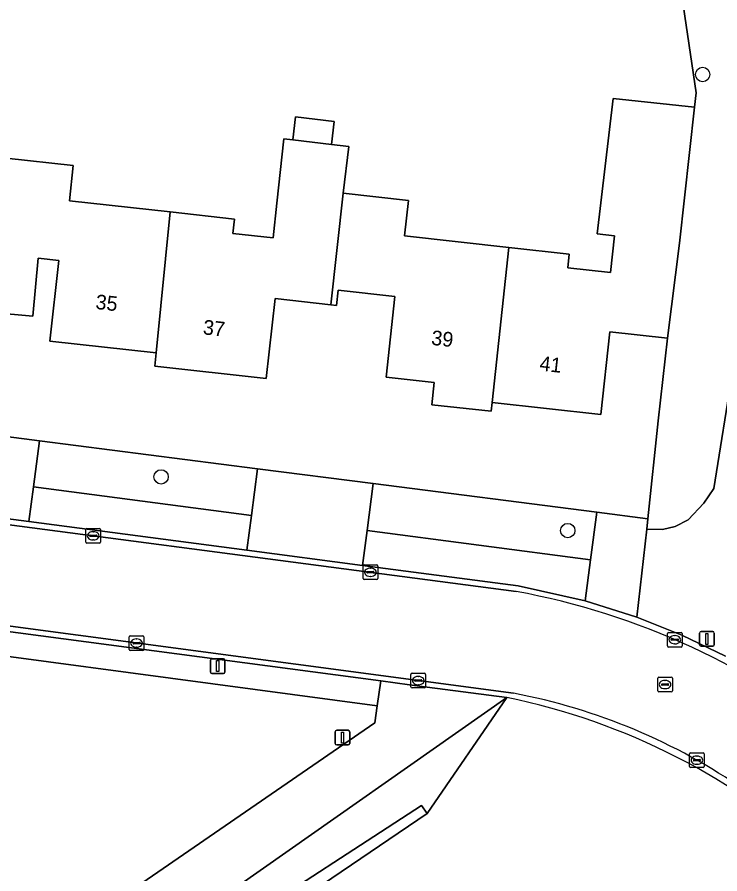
# Model space of a CAD drawing. Extents: x 162156 to 163172, y 378995 to 380779.
# Drawn here: x 162554.9 to 162602.7, y 380372 to 380430.3 of the extents above; entities that cross this region are included whole.
import ezdxf

# ---------------------------------------------------------------- set-up
doc = ezdxf.new("R2010")
doc.units = 0
for name, color, linetype in [('IMGEO_Berm_groen', 7, 'Continuous'), ('IMGEO_Boom', 7, 'Continuous'), ('IMGEO_Erf', 7, 'Continuous'), ('IMGEO_Grasland_overig', 7, 'Continuous'), ('IMGEO_Groenvoorziening', 7, 'Continuous'), ('IMGEO_Kolk', 7, 'Continuous'), ('IMGEO_Lichtmast', 7, 'Continuous'), ('IMGEO_Loofbos', 7, 'Continuous'), ('IMGEO_Naaldbos', 7, 'Continuous'), ('IMGEO_Pand', 7, 'Continuous'), ('IMGEO_Pand_nummerreeks', 7, 'Continuous'), ('IMGEO_Rijbaan_lokaal_gesloten', 7, 'Continuous'), ('IMGEO_Rioolput', 7, 'Continuous'), ('IMGEO_Voetpad_open', 7, 'Continuous'), ('IMGEO_Waterloop', 7, 'Continuous')]:
    doc.layers.add(name, color=color, linetype=linetype)

msp = doc.modelspace()

# ---------------------------------------------------------------- linework, layer by layer
at = {"layer": 'IMGEO_Berm_groen'}
for points in [[(162570.818, 380396.373), (162555.975, 380398.316), (162555.664, 380395.948), (162570.507, 380393.999)], [(162593.931, 380393.347), (162578.701, 380395.341), (162578.389, 380392.965), (162589.003, 380391.571), (162593.564, 380390.548)]]:
    msp.add_lwpolyline(points, close=True, dxfattribs=at)
at = {"layer": 'IMGEO_Boom'}
for centre in [(162601.57, 380426.397), (162564.669, 380398.997), (162592.38, 380395.341)]:
    msp.add_circle(centre, 0.489, dxfattribs=at)
at = {"layer": 'IMGEO_Erf'}
for points in [[(162554.109, 380420.701), (162558.682, 380420.192), (162558.416, 380417.799), (162565.287, 380417.035), (162569.664, 380416.548), (162569.556, 380415.575), (162572.306, 380415.269), (162572.559, 380417.632), (162573.028, 380422.024), (162573.635, 380421.951), (162573.822, 380423.507), (162576.464, 380423.19), (162576.277, 380421.634), (162577.451, 380421.493), (162577.069, 380418.312), (162581.524, 380417.816), (162581.256, 380415.406), (162588.352, 380414.617), (162592.475, 380414.158), (162592.372, 380413.232), (162595.29, 380412.908), (162595.568, 380415.405), (162594.377, 380415.538), (162595.473, 380424.77), (162601.019, 380424.181), (162601.125, 380425.141), (162599.269, 380437.761)], [(162548.501, 380402.47), (162556.387, 380401.459), (162571.235, 380399.555), (162579.121, 380398.544), (162594.356, 380396.59), (162597.84, 380396.144), (162598.548, 380402.803), (162599.176, 380408.437), (162595.256, 380408.873), (162594.629, 380403.239), (162587.218, 380404.064), (162587.153, 380403.462), (162583.112, 380403.911), (162583.281, 380405.431), (162579.994, 380405.797), (162580.602, 380411.271), (162576.742, 380411.701), (162576.628, 380410.676), (162576.226, 380410.721), (162572.44, 380411.142), (162571.834, 380405.691), (162564.238, 380406.536), (162564.328, 380407.439), (162557.097, 380408.244), (162557.707, 380413.723), (162556.282, 380413.881), (162555.936, 380409.935), (162553.143, 380410.179)]]:
    msp.add_lwpolyline(points, dxfattribs=at)
at = {"layer": 'IMGEO_Grasland_overig'}
for points in [[(162570.818, 380396.373), (162571.235, 380399.555), (162556.387, 380401.459), (162555.975, 380398.316)], [(162593.931, 380393.347), (162594.356, 380396.59), (162579.121, 380398.544), (162578.701, 380395.341)]]:
    msp.add_lwpolyline(points, close=True, dxfattribs=at)
at = {"layer": 'IMGEO_Groenvoorziening'}
for points in [[(162603.149, 380451.149), (162602.316, 380456.226), (162596.531, 380456.495), (162597.555, 380449.385), (162598.114, 380445.6), (162598.662, 380441.849), (162598.937, 380439.632), (162598.286, 380437.854), (162599.269, 380437.761), (162601.125, 380425.141), (162601.019, 380424.181), (162599.997, 380414.912), (162599.176, 380408.437), (162598.548, 380402.803), (162597.84, 380396.144), (162597.76, 380395.446), (162598.834, 380395.404), (162599.697, 380395.608), (162600.573, 380396.065), (162601.653, 380397.207), (162602.326, 380398.21), (162603.622, 380406.286)], [(162603.622, 380406.286), (162602.326, 380398.21), (162601.653, 380397.207), (162600.573, 380396.065), (162599.697, 380395.608), (162598.834, 380395.404), (162597.76, 380395.446), (162597.075, 380389.437), (162600.149, 380388.214), (162603.133, 380386.785)]]:
    msp.add_lwpolyline(points, dxfattribs=at)
msp.add_lwpolyline([(162515.462, 380331.725), (162532.467, 380343.441), (162569.479, 380368.209), (162582.423, 380376.619), (162582.8, 380376.077), (162588.216, 380383.966), (162569.893, 380371.126), (162550.741, 380358.23), (162527.032, 380341.73), (162514.906, 380333.495)], close=True, dxfattribs=at)
at = {"layer": 'IMGEO_Kolk'}
for p, q in [((162559.616, 380395.484), (162560.468, 380395.484)), ((162559.541, 380394.558), (162559.541, 380395.41)), ((162559.8, 380394.978), (162559.8, 380394.99)), ((162560.238, 380394.941), (162559.84, 380394.941)), ((162559.843, 380395.027), (162560.241, 380395.027)), ((162560.029, 380395.264), (162560.054, 380395.264)), ((162560.284, 380394.99), (162560.284, 380394.978)), ((162560.542, 380395.41), (162560.542, 380394.558)), ((162560.468, 380394.484), (162559.616, 380394.484)), ((162560.052, 380394.704), (162560.027, 380394.704)), ((162578.428, 380392.074), (162578.428, 380392.926)), ((162578.503, 380393), (162579.355, 380393)), ((162578.73, 380392.543), (162579.128, 380392.543)), ((162578.916, 380392.78), (162578.941, 380392.78)), ((162579.429, 380392.926), (162579.429, 380392.074)), ((162579.355, 380392), (162578.503, 380392)), ((162578.687, 380392.494), (162578.687, 380392.506)), ((162579.125, 380392.457), (162578.727, 380392.457)), ((162578.939, 380392.22), (162578.914, 380392.22)), ((162579.171, 380392.506), (162579.171, 380392.494)), ((162562.492, 380387.252), (162562.492, 380388.104)), ((162562.567, 380388.178), (162563.419, 380388.178)), ((162562.98, 380387.958), (162563.005, 380387.958)), ((162563.493, 380388.104), (162563.493, 380387.252)), ((162599.174, 380387.483), (162599.174, 380388.335)), ((162599.249, 380388.409), (162600.101, 380388.409)), ((162599.433, 380387.903), (162599.433, 380387.915)), ((162599.871, 380387.866), (162599.473, 380387.866)), ((162599.476, 380387.952), (162599.874, 380387.952)), ((162599.662, 380388.189), (162599.687, 380388.189)), ((162599.917, 380387.915), (162599.917, 380387.903)), ((162600.175, 380388.335), (162600.175, 380387.483)), ((162562.751, 380387.672), (162562.751, 380387.684)), ((162563.189, 380387.635), (162562.791, 380387.635)), ((162562.794, 380387.721), (162563.192, 380387.721)), ((162563.003, 380387.398), (162562.978, 380387.398)), ((162563.235, 380387.684), (162563.235, 380387.672)), ((162600.101, 380387.409), (162599.249, 380387.409)), ((162599.685, 380387.629), (162599.66, 380387.629)), ((162563.419, 380387.178), (162562.567, 380387.178)), ((162581.69, 380384.697), (162581.69, 380385.549)), ((162581.765, 380385.623), (162582.617, 380385.623)), ((162582.691, 380385.549), (162582.691, 380384.697)), ((162581.949, 380385.117), (162581.949, 380385.129)), ((162582.387, 380385.08), (162581.989, 380385.08)), ((162581.992, 380385.166), (162582.39, 380385.166)), ((162582.178, 380385.403), (162582.203, 380385.403)), ((162582.433, 380385.129), (162582.433, 380385.117)), ((162582.617, 380384.623), (162581.765, 380384.623)), ((162582.201, 380384.843), (162582.176, 380384.843)), ((162600.677, 380379.276), (162600.677, 380380.128)), ((162600.752, 380380.202), (162601.604, 380380.202)), ((162600.936, 380379.696), (162600.936, 380379.708)), ((162600.979, 380379.745), (162601.377, 380379.745)), ((162601.165, 380379.982), (162601.19, 380379.982)), ((162601.42, 380379.708), (162601.42, 380379.696)), ((162601.678, 380380.128), (162601.678, 380379.276)), ((162601.604, 380379.202), (162600.752, 380379.202)), ((162601.374, 380379.659), (162600.976, 380379.659)), ((162601.188, 380379.422), (162601.163, 380379.422))]:
    msp.add_line(p, q, dxfattribs=at)
for points in [[(162559.616, 380395.484), (162560.468, 380395.484)], [(162559.541, 380394.558), (162559.541, 380395.41)], [(162560.542, 380395.41), (162560.542, 380394.558)], [(162560.468, 380394.484), (162559.616, 380394.484)], [(162578.428, 380392.074), (162578.428, 380392.926)], [(162578.503, 380393), (162579.355, 380393)], [(162579.429, 380392.926), (162579.429, 380392.074)], [(162579.355, 380392), (162578.503, 380392)], [(162562.492, 380387.252), (162562.492, 380388.104)], [(162562.567, 380388.178), (162563.419, 380388.178)], [(162563.493, 380388.104), (162563.493, 380387.252)], [(162599.174, 380387.483), (162599.174, 380388.335)], [(162599.249, 380388.409), (162600.101, 380388.409)], [(162600.175, 380388.335), (162600.175, 380387.483)], [(162600.101, 380387.409), (162599.249, 380387.409)], [(162563.419, 380387.178), (162562.567, 380387.178)], [(162581.69, 380384.697), (162581.69, 380385.549)], [(162581.765, 380385.623), (162582.617, 380385.623)], [(162582.691, 380385.549), (162582.691, 380384.697)], [(162582.617, 380384.623), (162581.765, 380384.623)], [(162600.677, 380379.276), (162600.677, 380380.128)], [(162600.752, 380380.202), (162601.604, 380380.202)], [(162601.678, 380380.128), (162601.678, 380379.276)], [(162601.604, 380379.202), (162600.752, 380379.202)]]:
    msp.add_lwpolyline(points, dxfattribs=at)
for centre, radius, start, end in [((162559.618, 380395.408), 0.0765, 91.55205, 178.44795), ((162559.618, 380395.408), 0.0765, 91.55205, 178.44795), ((162560.466, 380395.408), 0.0765, 1.55205, 88.44795), ((162560.466, 380395.408), 0.0765, 1.55205, 88.44795), ((162559.84, 380394.987), 0.0403, 85.87752, 175.75265), ((162559.837, 380394.977), 0.0366, 178.93798, 274.71019), ((162560.241, 380394.984), 0.043, 264.86636, 352.45326), ((162560.245, 380394.989), 0.0386, 1.73085, 96.63898), ((162559.618, 380394.56), 0.0765, 181.55205, 268.44795), ((162559.618, 380394.56), 0.0765, 181.55205, 268.44795), ((162560.466, 380394.56), 0.0765, 271.55205, 358.44795), ((162560.466, 380394.56), 0.0765, 271.55205, 358.44795), ((162578.505, 380392.924), 0.0765, 91.55205, 178.44795), ((162578.505, 380392.924), 0.0765, 91.55205, 178.44795), ((162578.727, 380392.503), 0.0403, 85.87752, 175.75265), ((162579.132, 380392.505), 0.0386, 1.73085, 96.63898), ((162579.353, 380392.924), 0.0765, 1.55205, 88.44795), ((162579.353, 380392.924), 0.0765, 1.55205, 88.44795), ((162578.505, 380392.076), 0.0765, 181.55205, 268.44795), ((162578.505, 380392.076), 0.0765, 181.55205, 268.44795), ((162578.724, 380392.493), 0.0366, 178.93798, 274.71019), ((162579.128, 380392.5), 0.043, 264.86636, 352.45326), ((162579.353, 380392.076), 0.0765, 271.55205, 358.44795), ((162579.353, 380392.076), 0.0765, 271.55205, 358.44795), ((162562.569, 380388.102), 0.0765, 91.55205, 178.44795), ((162562.569, 380388.102), 0.0765, 91.55205, 178.44795), ((162563.417, 380388.102), 0.0765, 1.55205, 88.44795), ((162563.417, 380388.102), 0.0765, 1.55205, 88.44795), ((162599.251, 380388.333), 0.0765, 91.55205, 178.44795), ((162599.251, 380388.333), 0.0765, 91.55205, 178.44795), ((162599.473, 380387.912), 0.0403, 85.87752, 175.75265), ((162599.47, 380387.902), 0.0366, 178.93798, 274.71019), ((162599.874, 380387.909), 0.043, 264.86636, 352.45326), ((162599.878, 380387.914), 0.0386, 1.73085, 96.63898), ((162600.099, 380388.333), 0.0765, 1.55205, 88.44795), ((162600.099, 380388.333), 0.0765, 1.55205, 88.44795), ((162562.791, 380387.681), 0.0403, 85.87752, 175.75265), ((162562.788, 380387.671), 0.0366, 178.93798, 274.71019), ((162563.192, 380387.678), 0.043, 264.86636, 352.45326), ((162563.196, 380387.683), 0.0386, 1.73085, 96.63898), ((162599.251, 380387.485), 0.0765, 181.55205, 268.44795), ((162599.251, 380387.485), 0.0765, 181.55205, 268.44795), ((162600.099, 380387.485), 0.0765, 271.55205, 358.44795), ((162600.099, 380387.485), 0.0765, 271.55205, 358.44795), ((162562.569, 380387.254), 0.0765, 181.55205, 268.44795), ((162562.569, 380387.254), 0.0765, 181.55205, 268.44795), ((162563.417, 380387.254), 0.0765, 271.55205, 358.44795), ((162563.417, 380387.254), 0.0765, 271.55205, 358.44795), ((162581.767, 380385.547), 0.0765, 91.55205, 178.44795), ((162581.767, 380385.547), 0.0765, 91.55205, 178.44795), ((162582.615, 380385.547), 0.0765, 1.55205, 88.44795), ((162582.615, 380385.547), 0.0765, 1.55205, 88.44795), ((162581.989, 380385.126), 0.0403, 85.87752, 175.75265), ((162581.986, 380385.116), 0.0366, 178.93798, 274.71019), ((162582.39, 380385.123), 0.043, 264.86636, 352.45326), ((162582.394, 380385.128), 0.0386, 1.73085, 96.63898), ((162581.767, 380384.699), 0.0765, 181.55205, 268.44795), ((162581.767, 380384.699), 0.0765, 181.55205, 268.44795), ((162582.615, 380384.699), 0.0765, 271.55205, 358.44795), ((162582.615, 380384.699), 0.0765, 271.55205, 358.44795), ((162600.754, 380380.126), 0.0765, 91.55205, 178.44795), ((162600.754, 380380.126), 0.0765, 91.55205, 178.44795), ((162600.976, 380379.705), 0.0403, 85.87752, 175.75265), ((162600.973, 380379.695), 0.0366, 178.93798, 274.71019), ((162601.377, 380379.702), 0.043, 264.86636, 352.45326), ((162601.381, 380379.707), 0.0386, 1.73085, 96.63898), ((162601.602, 380380.126), 0.0765, 1.55205, 88.44795), ((162601.602, 380380.126), 0.0765, 1.55205, 88.44795), ((162600.754, 380379.278), 0.0765, 181.55205, 268.44795), ((162600.754, 380379.278), 0.0765, 181.55205, 268.44795), ((162601.602, 380379.278), 0.0765, 271.55205, 358.44795), ((162601.602, 380379.278), 0.0765, 271.55205, 358.44795)]:
    msp.add_arc(centre, radius, start, end, dxfattribs=at)
for centre, major_axis, ratio, start_param, end_param in [((162560.028, 380394.984), (-0.387, 0.002), 0.722429, 4.712389, 7.853982), ((162560.053, 380394.984), (-0.39, 0.002), 0.717154, 1.570796, 4.712389), ((162578.915, 380392.5), (-0.387, 0.002), 0.722429, 4.712389, 7.853982), ((162578.94, 380392.5), (-0.39, 0.002), 0.717154, 1.570796, 4.712389), ((162562.979, 380387.678), (-0.387, 0.002), 0.722429, 4.712389, 7.853982), ((162563.004, 380387.678), (-0.39, 0.002), 0.717154, 1.570796, 4.712389), ((162599.661, 380387.909), (-0.387, 0.002), 0.722429, 4.712389, 7.853982), ((162599.686, 380387.909), (-0.39, 0.002), 0.717154, 1.570796, 4.712389), ((162582.177, 380385.123), (-0.387, 0.002), 0.722429, 4.712389, 7.853982), ((162582.202, 380385.123), (-0.39, 0.002), 0.717154, 1.570796, 4.712389), ((162601.164, 380379.702), (-0.387, 0.002), 0.722429, 4.712389, 7.853982), ((162601.189, 380379.702), (-0.39, 0.002), 0.717154, 1.570796, 4.712389)]:
    msp.add_ellipse(centre, major_axis=major_axis, ratio=ratio, start_param=start_param, end_param=end_param, dxfattribs=at)
at = {"layer": 'IMGEO_Lichtmast'}
for p, q in [((162601.463, 380388.464), (162602.253, 380388.464)), ((162602.253, 380388.464), (162601.463, 380388.464)), ((162601.363, 380387.564), (162601.363, 380388.364)), ((162601.363, 380388.364), (162601.363, 380387.564)), ((162602.353, 380388.364), (162602.353, 380387.564)), ((162602.353, 380387.564), (162602.353, 380388.364)), ((162602.253, 380387.464), (162601.463, 380387.464)), ((162601.463, 380387.464), (162602.253, 380387.464)), ((162568.027, 380385.709), (162568.027, 380386.509)), ((162568.027, 380386.509), (162568.027, 380385.709)), ((162568.127, 380386.609), (162568.917, 380386.609)), ((162568.917, 380386.609), (162568.127, 380386.609)), ((162569.017, 380386.509), (162569.017, 380385.709)), ((162569.017, 380385.709), (162569.017, 380386.509)), ((162568.917, 380385.609), (162568.127, 380385.609)), ((162568.127, 380385.609), (162568.917, 380385.609)), ((162576.533, 380380.843), (162576.533, 380381.643)), ((162576.533, 380381.643), (162576.533, 380380.843)), ((162576.633, 380381.743), (162577.423, 380381.743)), ((162577.423, 380381.743), (162576.633, 380381.743)), ((162577.523, 380381.643), (162577.523, 380380.843)), ((162577.523, 380380.843), (162577.523, 380381.643)), ((162577.423, 380380.743), (162576.633, 380380.743)), ((162576.633, 380380.743), (162577.423, 380380.743))]:
    msp.add_line(p, q, dxfattribs=at)
for points in [[(162601.783, 380388.339), (162601.933, 380388.339), (162601.933, 380387.589), (162601.783, 380387.589), (162601.783, 380388.339)], [(162568.447, 380386.484), (162568.597, 380386.484), (162568.597, 380385.734), (162568.447, 380385.734), (162568.447, 380386.484)], [(162576.953, 380381.618), (162577.103, 380381.618), (162577.103, 380380.868), (162576.953, 380380.868), (162576.953, 380381.618)]]:
    msp.add_lwpolyline(points, dxfattribs=at)
for centre, start, end in [((162601.463, 380388.364), 90, 180), ((162601.463, 380388.364), 90, 180), ((162602.253, 380388.364), 0, 90), ((162602.253, 380388.364), 360, 90), ((162601.463, 380387.564), 180, 270), ((162601.463, 380387.564), 180, 270), ((162602.253, 380387.564), 270, 0), ((162602.253, 380387.564), 270, 0), ((162568.127, 380386.509), 90, 180), ((162568.127, 380386.509), 90, 180), ((162568.917, 380386.509), 0, 90), ((162568.917, 380386.509), 360, 90), ((162568.127, 380385.709), 180, 270), ((162568.127, 380385.709), 180, 270), ((162568.917, 380385.709), 270, 0), ((162568.917, 380385.709), 270, 0), ((162576.633, 380381.643), 90, 180), ((162576.633, 380381.643), 90, 180), ((162577.423, 380381.643), 0, 90), ((162577.423, 380381.643), 360, 90), ((162576.633, 380380.843), 180, 270), ((162576.633, 380380.843), 180, 270), ((162577.423, 380380.843), 270, 0), ((162577.423, 380380.843), 270, 0)]:
    msp.add_arc(centre, 0.1, start, end, dxfattribs=at)
at = {"layer": 'IMGEO_Loofbos'}
msp.add_lwpolyline([(162500.64, 380393.934), (162508.876, 380361.55), (162514.474, 380338.224), (162516.797, 380339.803), (162548.918, 380361.419), (162579.241, 380382.243), (162579.396, 380383.398)], close=True, dxfattribs=at)
at = {"layer": 'IMGEO_Naaldbos'}
msp.add_lwpolyline([(162588.216, 380383.966), (162582.8, 380376.077), (162542.599, 380348.845), (162515.929, 380330.238)], dxfattribs=at)
msp.add_arc((162579.125, 380339.41), 45.474, 47.48366, 78.4686, dxfattribs=at)
at = {"layer": 'IMGEO_Pand'}
for points in [[(162587.218, 380404.064), (162594.629, 380403.239), (162595.256, 380408.873), (162599.176, 380408.437), (162599.997, 380414.912), (162601.019, 380424.181), (162595.473, 380424.77), (162594.377, 380415.538), (162595.568, 380415.405), (162595.29, 380412.908), (162592.372, 380413.232), (162592.475, 380414.158), (162588.352, 380414.617)], [(162573.635, 380421.951), (162576.277, 380421.634), (162576.464, 380423.19), (162573.822, 380423.507)], [(162577.069, 380418.312), (162577.451, 380421.493), (162576.277, 380421.634), (162573.635, 380421.951), (162573.028, 380422.024), (162572.559, 380417.632), (162572.306, 380415.269), (162569.556, 380415.575), (162569.664, 380416.548), (162565.287, 380417.035), (162564.328, 380407.439), (162564.238, 380406.536), (162571.834, 380405.691), (162572.44, 380411.142), (162576.226, 380410.721)], [(162565.287, 380417.035), (162558.416, 380417.799), (162558.682, 380420.192), (162554.109, 380420.701), (162553.897, 380418.789), (162553.804, 380417.725), (162553.232, 380411.199), (162553.143, 380410.179), (162555.936, 380409.935), (162556.282, 380413.881), (162557.707, 380413.723), (162557.097, 380408.244), (162564.328, 380407.439)], [(162588.352, 380414.617), (162581.256, 380415.406), (162581.524, 380417.816), (162577.069, 380418.312), (162576.226, 380410.721), (162576.628, 380410.676), (162576.742, 380411.701), (162580.602, 380411.271), (162579.994, 380405.797), (162583.281, 380405.431), (162583.112, 380403.911), (162587.153, 380403.462), (162587.218, 380404.064)]]:
    msp.add_lwpolyline(points, close=True, dxfattribs=at)
at = {"layer": 'IMGEO_Rijbaan_lokaal_gesloten'}
for points in [[(162603.133, 380386.785), (162600.149, 380388.214), (162597.075, 380389.437), (162593.564, 380390.548), (162589.003, 380391.571), (162578.389, 380392.965), (162570.507, 380393.999), (162555.664, 380395.948), (162547.782, 380396.983), (162530.926, 380399.196), (162527.098, 380399.699), (162522.161, 380400.351), (162522.113, 380400.03), (162541.537, 380397.415), (162588.854, 380391.194)], [(162588.854, 380391.194), (162541.537, 380397.415), (162522.113, 380400.03), (162522.1, 380400.031), (162521.145, 380393.198), (162544.152, 380390.187), (162588.674, 380384.26)], [(162588.674, 380384.26), (162544.152, 380390.187), (162521.145, 380393.198), (162521.087, 380392.822), (162544.102, 380389.81), (162579.648, 380385.1), (162581.598, 380384.842), (162582.796, 380384.684), (162588.216, 380383.966)], [(162514.906, 380333.495), (162527.032, 380341.73), (162550.741, 380358.23), (162569.893, 380371.126), (162588.216, 380383.966), (162582.796, 380384.684), (162581.598, 380384.842), (162579.648, 380385.1), (162579.396, 380383.398), (162579.241, 380382.243), (162548.918, 380361.419), (162516.797, 380339.803), (162514.474, 380338.224), (162511.615, 380336.281), (162490.341, 380321.822)]]:
    msp.add_lwpolyline(points, dxfattribs=at)
for centre, radius, start, end in [((162579.816, 380341.992), 50.025, 50.73885, 79.59175), ((162579.816, 380341.992), 50.025, 50.73885, 79.59175), ((162579.125, 380339.41), 45.474, 47.48366, 78.4686), ((162581.125, 380344.105), 40.858, 55.1636, 79.35316), ((162581.125, 380344.105), 40.858, 55.1636, 79.35316)]:
    msp.add_arc(centre, radius, start, end, dxfattribs=at)
at = {"layer": 'IMGEO_Rioolput'}
for p, q in [((162598.506, 380384.428), (162598.506, 380385.28)), ((162598.581, 380385.354), (162599.433, 380385.354)), ((162598.994, 380385.134), (162599.019, 380385.134)), ((162599.507, 380385.28), (162599.507, 380384.428)), ((162599.433, 380384.354), (162598.581, 380384.354)), ((162598.765, 380384.848), (162598.765, 380384.86)), ((162599.203, 380384.811), (162598.805, 380384.811)), ((162598.808, 380384.897), (162599.206, 380384.897)), ((162599.017, 380384.574), (162598.992, 380384.574)), ((162599.249, 380384.86), (162599.249, 380384.848))]:
    msp.add_line(p, q, dxfattribs=at)
for points in [[(162598.506, 380384.428), (162598.506, 380385.28)], [(162598.581, 380385.354), (162599.433, 380385.354)], [(162599.507, 380385.28), (162599.507, 380384.428)], [(162599.433, 380384.354), (162598.581, 380384.354)]]:
    msp.add_lwpolyline(points, dxfattribs=at)
for centre, radius, start, end in [((162598.583, 380385.278), 0.0765, 91.55205, 178.44795), ((162598.583, 380385.278), 0.0765, 91.55205, 178.44795), ((162599.431, 380385.278), 0.0765, 1.55205, 88.44795), ((162599.431, 380385.278), 0.0765, 1.55205, 88.44795), ((162598.583, 380384.43), 0.0765, 181.55205, 268.44795), ((162598.583, 380384.43), 0.0765, 181.55205, 268.44795), ((162598.805, 380384.857), 0.0403, 85.87752, 175.75265), ((162598.802, 380384.847), 0.0366, 178.93798, 274.71019), ((162599.206, 380384.854), 0.043, 264.86636, 352.45326), ((162599.21, 380384.859), 0.0386, 1.73085, 96.63898), ((162599.431, 380384.43), 0.0765, 271.55205, 358.44795), ((162599.431, 380384.43), 0.0765, 271.55205, 358.44795)]:
    msp.add_arc(centre, radius, start, end, dxfattribs=at)
for centre, major_axis, ratio, start_param, end_param in [((162598.993, 380384.854), (-0.387, 0.002), 0.722429, 4.712389, 7.853982), ((162599.018, 380384.854), (-0.39, 0.002), 0.717154, 1.570796, 4.712389)]:
    msp.add_ellipse(centre, major_axis=major_axis, ratio=ratio, start_param=start_param, end_param=end_param, dxfattribs=at)
at = {"layer": 'IMGEO_Voetpad_open'}
msp.add_lwpolyline([(162329.788, 380406.31), (162330.761, 380406.226), (162338.342, 380405.57), (162392.234, 380403.338), (162422.555, 380402.082), (162437.447, 380401.191), (162459.542, 380399.35), (162483.054, 380396.268), (162486.399, 380395.83), (162491.443, 380395.165), (162497.556, 380394.347), (162500, 380394.02), (162500.64, 380393.934), (162579.396, 380383.398), (162579.648, 380385.1), (162544.102, 380389.81), (162521.087, 380392.822), (162509.445, 380394.346), (162500, 380395.64), (162478.546, 380398.575), (162459.366, 380401.173)], dxfattribs=at)
for points in [[(162548.066, 380399.15), (162547.782, 380396.983), (162555.664, 380395.948), (162555.975, 380398.316), (162556.387, 380401.459), (162548.501, 380402.47)], [(162570.818, 380396.373), (162570.507, 380393.999), (162578.389, 380392.965), (162578.701, 380395.341), (162579.121, 380398.544), (162571.235, 380399.555)], [(162597.075, 380389.437), (162597.76, 380395.446), (162597.84, 380396.144), (162594.356, 380396.59), (162593.931, 380393.347), (162593.564, 380390.548)]]:
    msp.add_lwpolyline(points, close=True, dxfattribs=at)
at = {"layer": 'IMGEO_Waterloop'}
msp.add_lwpolyline([(162515.929, 380330.238), (162542.599, 380348.845), (162582.8, 380376.077), (162582.423, 380376.619), (162569.479, 380368.209), (162532.467, 380343.441), (162515.462, 380331.725)], close=True, dxfattribs=at)

# ---------------------------------------------------------------- texts
at = {"layer": 'IMGEO_Pand_nummerreeks'}
for s, rotation, p in [('35', 353.65163, (162560.167, 380410.437)), ('37', 353.65163, (162567.485, 380408.71)), ('39', 353.65163, (162583.043, 380407.993)), ('41', 353.64649, (162590.422, 380406.244))]:
    msp.add_text(s, height=1, rotation=rotation, dxfattribs=at).set_placement(p)

doc.saveas('drawing.dxf')
